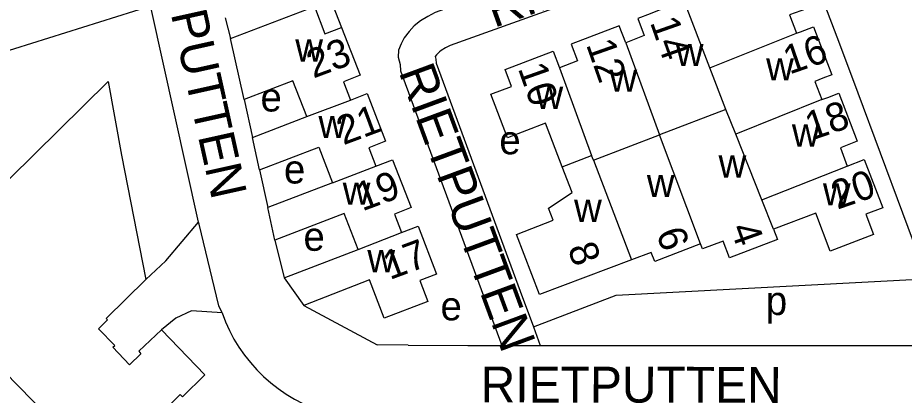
# Model space of a CAD drawing. Extents: x 159261 to 160849, y 382514 to 384534.
# Drawn here: x 159387.5 to 159511.1, y 383631.8 to 383684.3 of the extents above; entities that cross this region are included whole.
import ezdxf

# ---------------------------------------------------------------- set-up
doc = ezdxf.new("R2010")
doc.units = 0
for name, color, linetype in [('BLT_Basislijn', 7, 'Continuous'), ('BLT_Bebouwing', 7, 'Continuous'), ('BLT_Centroide', 7, 'Continuous'), ('BLT_Huisnummer', 7, 'Continuous'), ('BLT_Huisnummer_ tussenligend', 7, 'Continuous'), ('BLT_Onderverdeling_panden', 7, 'Continuous'), ('BLT_Straatnaam', 7, 'Continuous')]:
    doc.layers.add(name, color=color, linetype=linetype)

msp = doc.modelspace()

# ---------------------------------------------------------------- linework, layer by layer
at = {"layer": 'BLT_Basislijn'}
for p, q in [((159495.6, 383697.65), (159502.02, 383680.72)), ((159349.98, 383668.51), (159405.99, 383686.02)), ((159412.68, 383655.86), (159406.07, 383685.64)), ((159431.36, 383686.19), (159432.61, 383683.01)), ((159416.39, 383684.35), (159417.14, 383681.46)), ((159502.02, 383680.72), (159504.59, 383673.88)), ((159419.01, 383672.95), (159420.17, 383667.67)), ((159504.59, 383673.88), (159514.2, 383647.98)), ((159421.17, 383663.17), (159422.32, 383657.91)), ((159423.31, 383653.38), (159424.58, 383648.12)), ((159470.88, 383645.72), (159514.2, 383647.98)), ((159457.51, 383646.28), (159459.34, 383641.31)), ((159459.34, 383641.31), (159470.88, 383645.72)), ((159459.34, 383641.31), (159460.3, 383638.71)), ((159441.9, 383638.74), (159437.58, 383638.81)), ((159441.9, 383638.74), (159450.19, 383638.71)), ((159450.19, 383638.71), (159454.95, 383638.71)), ((159454.95, 383638.71), (159460.3, 383638.71)), ((159460.3, 383638.71), (159460.76, 383638.71))]:
    msp.add_line(p, q, dxfattribs=at)
for points in [[(159493.83, 383702.35), (159445.65, 383685.08), (159444.65, 383684.53), (159443.6, 383683.94), (159442.74, 383683.21), (159442.02, 383682.41), (159441.34, 383681.56), (159440.92, 383680.7), (159440.53, 383679.82)], [(159495.6, 383697.65), (159447.72, 383680.49), (159447.09, 383680.14), (159446.48, 383679.8), (159446.24, 383679.6), (159445.85, 383679.16), (159445.66, 383678.93), (159445.74, 383678.6), (159445.78, 383678.03), (159457.51, 383646.28)], [(159440.53, 383679.82), (159440.51, 383678.87), (159440.76, 383677.83), (159440.82, 383676.97), (159454.95, 383638.71)], [(159405.3, 383647.88), (159408.1, 383650.48), (159412.68, 383655.86)], [(159415.94, 383643.23), (159415.48, 383644.2), (159412.74, 383655.58), (159412.68, 383655.86)], [(159460.76, 383638.71), (159512.56, 383638.7), (159513.63, 383638.9), (159515.58, 383640.39), (159516.01, 383642.39), (159515.46, 383644.62)], [(159415.94, 383643.23), (159411.69, 383643.54), (159409.48, 383642.5), (159407.48, 383640.88)], [(159427.33, 383644.27), (159437.58, 383638.81)], [(159415.94, 383643.23), (159416.42, 383641.99), (159416.98, 383640.77), (159417.6, 383639.6), (159418.3, 383638.46), (159419.06, 383637.36), (159419.89, 383636.32), (159420.78, 383635.33), (159421.73, 383634.39), (159422.73, 383633.51), (159423.78, 383632.69), (159424.88, 383631.93), (159426.02, 383631.24), (159427.2, 383630.63), (159428.42, 383630.08), (159429.67, 383629.61), (159430.94, 383629.21), (159432.24, 383628.9), (159433.55, 383628.65), (159434.87, 383628.49), (159436.2, 383628.41), (159437.4, 383628.41)]]:
    msp.add_lwpolyline(points, dxfattribs=at)
at = {"layer": 'BLT_Bebouwing'}
for p, q in [((159419.01, 383672.95), (159417.14, 383681.46)), ((159401.93, 383665.21), (159405.3, 383647.88)), ((159423.31, 383653.38), (159422.32, 383657.91)), ((159424.58, 383648.12), (159434.9, 383652.07)), ((159424.58, 383648.12), (159427.33, 383644.27))]:
    msp.add_line(p, q, dxfattribs=at)
for points in [[(159480.34, 383686.78), (159475.64, 383684.89), (159473.89, 383684.22), (159474.8, 383681.86), (159472.22, 383680.87)], [(159417.14, 383681.46), (159428.82, 383685.93), (159430.27, 383682.12), (159432.61, 383683.01)], [(159497.42, 383685.6), (159495.05, 383684.74), (159496.03, 383682.2)], [(159432.61, 383683.01), (159435.19, 383676.36)], [(159471.32, 383683.24), (159464.62, 383680.68), (159465.51, 383678.33), (159462.97, 383677.36)], [(159472.22, 383680.87), (159471.32, 383683.24)], [(159496.03, 383682.2), (159496.57, 383682.4), (159498.38, 383683.1), (159500.94, 383676.4), (159499.7, 383675.91)], [(159463.35, 383663.6), (159461.02, 383669.67), (159455.74, 383667.64), (159453.42, 383673.69), (159456.29, 383674.79), (159455.39, 383677.14), (159462.08, 383679.7), (159462.97, 383677.36)], [(159376.05, 383651.84), (159400.05, 383675.46), (159401.93, 383665.21)], [(159427.77, 383670.58), (159425.83, 383675.56), (159419.01, 383672.95)], [(159435.19, 383676.36), (159432.86, 383675.43), (159433.84, 383672.87)], [(159499.7, 383675.91), (159498.6, 383675.49), (159499.57, 383672.95)], [(159433.84, 383672.87), (159436.18, 383673.81), (159438.74, 383667.16), (159436.42, 383666.22), (159437.4, 383663.66)], [(159499.57, 383672.95), (159500.38, 383673.26), (159501.93, 383673.85), (159504.48, 383667.15), (159502.14, 383666.25), (159503.11, 383663.69)], [(159420.17, 383667.67), (159427.77, 383670.58)], [(159421.17, 383663.17), (159420.17, 383667.67)], [(159421.17, 383663.17), (159429.45, 383666.33), (159431.35, 383661.37)], [(159437.4, 383663.66), (159439.72, 383664.56), (159442.29, 383657.92), (159439.96, 383656.98), (159440.94, 383654.42)], [(159503.11, 383663.69), (159505.47, 383664.59), (159508.06, 383657.89), (159505.68, 383656.99), (159506.77, 383654.15), (159500.71, 383651.84), (159498.7, 383657.12), (159492.81, 383654.88)], [(159473.04, 383650.62), (159460.2, 383645.78), (159457, 383654.18), (159462.08, 383656.14), (159461.43, 383657.82), (159464.75, 383659.99), (159463.35, 383663.6)], [(159431.35, 383661.37), (159422.32, 383657.91)], [(159434.9, 383652.07), (159432.95, 383657.07), (159423.31, 383653.38)], [(159440.94, 383654.42), (159443.29, 383655.32), (159445.84, 383648.64), (159443.51, 383647.73), (159444.62, 383644.83), (159438.56, 383642.51), (159436.51, 383647.85), (159427.33, 383644.27)], [(159492.81, 383654.88), (159493.36, 383653.44), (159486.69, 383650.89), (159485.78, 383653.24), (159482.91, 383652.15), (159482.62, 383652.84)], [(159482.62, 383652.84), (159476.28, 383650.41), (159475.78, 383651.66), (159473.04, 383650.62)], [(159407.48, 383640.88), (159404.32, 383637.89), (159404.62, 383637.55), (159403.06, 383636.01), (159400.7, 383638.45), (159400.97, 383638.7), (159398.7, 383641.02), (159399.96, 383642.26), (159399.77, 383642.47), (159405.3, 383647.88)], [(159414.91, 383604.83), (159414.91, 383605.09), (159377.74, 383643)], [(159441.32, 383622.41), (159416.28, 383622.63), (159408.65, 383630.42), (159410.11, 383631.88), (159410.41, 383631.56), (159413.55, 383634.59), (159407.48, 383640.88)]]:
    msp.add_lwpolyline(points, dxfattribs=at)
at = {"layer": 'BLT_Onderverdeling_panden'}
for p, q in [((159483.96, 383677.37), (159480.34, 383686.78)), ((159483.96, 383677.37), (159496.03, 383682.2)), ((159472.22, 383680.87), (159476.95, 383668.04)), ((159462.97, 383677.36), (159467.45, 383665.17)), ((159486.19, 383671.58), (159483.96, 383677.37)), ((159499.57, 383672.95), (159487.55, 383668.14)), ((159427.77, 383670.58), (159433.84, 383672.87)), ((159486.19, 383671.58), (159476.95, 383668.04)), ((159487.55, 383668.14), (159486.19, 383671.58)), ((159467.71, 383664.5), (159476.95, 383668.04)), ((159482.62, 383652.84), (159476.95, 383668.04)), ((159491.19, 383658.97), (159487.55, 383668.14)), ((159463.35, 383663.6), (159467.45, 383665.17)), ((159467.71, 383664.5), (159467.45, 383665.17)), ((159467.71, 383664.5), (159473.04, 383650.62)), ((159431.35, 383661.37), (159437.4, 383663.66)), ((159491.19, 383658.97), (159503.11, 383663.69)), ((159492.81, 383654.88), (159491.19, 383658.97)), ((159434.9, 383652.07), (159440.94, 383654.42))]:
    msp.add_line(p, q, dxfattribs=at)

# ---------------------------------------------------------------- texts
at = {"layer": 'BLT_Centroide'}
for s, p in [('w', (159426.15, 383678.25)), ('w', (159479.2, 383677.61)), ('w', (159491.79, 383675.62)), ('w', (159469.95, 383674.03)), ('e', (159421.3, 383671.29)), ('w', (159459.63, 383671.66)), ('w', (159429.38, 383667.59)), ('w', (159495.39, 383666.41)), ('e', (159454.6, 383665.33)), ('e', (159424.57, 383661.26)), ('w', (159485.16, 383662.09)), ('w', (159475.16, 383659.39)), ('w', (159432.76, 383658.31)), ('w', (159499.71, 383658.22)), ('w', (159465.02, 383655.92)), ('e', (159427.29, 383651.89)), ('w', (159436.2, 383648.91)), ('p', (159491.75, 383642.95)), ('e', (159446.4, 383642.2))]:
    msp.add_text(s, height=4, dxfattribs=at).set_placement(p)
at = {"layer": 'BLT_Huisnummer'}
for s, rotation, p in [('14', 289.3828, (159475.57, 383683.72)), ('23', 20.3608, (159428.66, 383675.87)), ('10', 289.3828, (159457.16, 383677.3)), ('20', 19.0324, (159501.71, 383657.6)), ('4', 289.5069, (159486.75, 383655.05)), ('17', 20.3608, (159439.32, 383647.8)), ('8', 289.5069, (159464.08, 383652.27))]:
    msp.add_text(s, height=4, rotation=rotation, dxfattribs=at).set_placement(p)
at = {"layer": 'BLT_Huisnummer_ tussenligend'}
for s, rotation, p in [('16', 19.0324, (159495.04, 383676.42)), ('12', 289.3828, (159466.66, 383680.62)), ('21', 20.3608, (159432.84, 383666.57)), ('18', 19.0324, (159498.08, 383667.21)), ('19', 20.3608, (159435.49, 383657.36)), ('6', 289.5069, (159476.43, 383654.36))]:
    msp.add_text(s, height=4, rotation=rotation, dxfattribs=at).set_placement(p)
at = {"layer": 'BLT_Straatnaam'}
for rotation, p in [(19.7198, (159453.87, 383682.91)), (282.5149, (159405.48, 383699.79)), (290.2634, (159440.53, 383676.81)), (359.9173, (159451.99, 383630.77))]:
    msp.add_text('RIETPUTTEN', height=5, rotation=rotation, dxfattribs=at).set_placement(p)

doc.saveas('drawing.dxf')
